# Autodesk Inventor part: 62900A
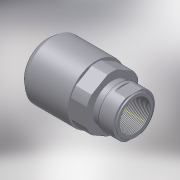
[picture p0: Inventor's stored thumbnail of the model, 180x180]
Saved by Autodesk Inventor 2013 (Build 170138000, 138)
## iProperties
Shininess: 25.0
Length Units: 11269
Angle Units: 11279
Time Units: 11290
Mass Units: 11283
Length Display Precision: 3
Angle Display Precision: 2
Created: 2002-07
Part Number: 62900A
Description: Дроссель с обратным клапаном 62900А ТУ22-5817-84
Document SubType Name: Modeling
Designer: SaAlex
Material: Steel, Mild
Density: 7.86 g/cm^3
Density: 0.0
Volumn: 0.0
Area: 0.0
PropertySet Name: Model Information
Control State: 0
Master: False
Checked Out: False
Checked Out Date: 2008-10-15
Last Check In Date: 2008-10-15
Author: SaAlex
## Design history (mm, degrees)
sketch "Sketch1"
  geometry: L1 (-67, 45)-(0, 45); L2 (-77, 36.5)-(-67, 45); L3 (-77, 36.5)-(-77, 32.5); L4 (-79, 32.5)-(-77, 32.5); L5 (-79, 30)-(-79, 32.5); L6 (-81, 30)-(-79, 30); L7 (-81, 0)-(-81, 30); L8 (-81, 0)-(0, 0); L9 (0, 45)-(0, 0); L10 (-81, 0)-(0, 0)
  constraints: 20 end point, 4 horizontal, 3 vertical, 1 other
  dimensions: "d67" = 81 distance between parallel lines of L9 L7; "d68" = 2 distance between parallel lines of L5 L7; "d69" = 2 distance between parallel lines of L3 L5; "d70" = 14 distance from line of L1.start L7; "d71" = 30 distance between parallel lines of L8 L6; "d72" = 32.5 distance between parallel lines of L8 L4; "d73" = 36.5 distance from line of L8 L2.start; "d75" = 45 distance from line of L8 L1.start
revolve "RevolutionFull1" sketch "Sketch1" stored, may be unused: angle "d0" = 360 deg
sketch "Sketch2"
  geometry: L1 (41.822, 7.563)-(27.46, 32.437); L2 (27.46, -32.437)-(41.822, -7.563); L3 (-14.361, -40)-(14.361, -40); L4 (-41.822, -7.563)-(-27.46, -32.437); L5 (-27.46, 32.437)-(-41.822, 7.563); L6 (14.361, 40)-(-14.361, 40); C1 r 40 at (0, 0); C2 r 45 at (0, 0) reference; A1 r 42.5 centre (0, 0) between (41.822, -7.563) and (41.822, 7.563); A2 r 42.5 centre (0, 0) between (14.361, -40) and (27.46, -32.437); A3 r 42.5 centre (0, 0) between (-27.46, -32.437) and (-14.361, -40); A4 r 42.5 centre (0, 0) between (-41.822, 7.563) and (-41.822, -7.563); A5 r 42.5 centre (0, 0) between (-14.361, 40) and (-27.46, 32.437); A6 r 42.5 centre (0, 0) between (27.46, 32.437) and (14.361, 40)
  constraints: 12 end point, 12 point on circle, 8 concentric, 7 centre point, 6 tangent, 2 horizontal, 1 coincident, 1 parallel
  dimensions: "d4" = 80 diameter of C1; "d6" = 42.5 radius of A5
extrude "ExtrusionBlind1" join sketch "Sketch2" distance "d7" = 25; taper "d8" = 0 deg
sketch "Sketch3"
  geometry: L1 (-29, 0)-(21, 0)
  constraints: 2 end point
node "WorkAxis1"
sketch "Sketch4"
  geometry: L1 (-25, 0)-(-36, 0); L2 (-25, 30)-(-25, 0); L3 (-36, 30)-(-25, 30); L4 (-36, 0)-(-36, 30); L5 (-25, -42.5)-(-25, -41.822) reference; L6 (-25, 0)-(-36, 0); L7 (104.4, 0)-(-59.4, 0) reference
  constraints: 10 end point, 2 collinear, 2 horizontal, 2 vertical
  dimensions: "d12" = 11 distance of L3.start L2.start; "d14" = 60 diameter of L3.start L1
revolve "RevolutionFull2" sketch "Sketch4" stored, may be unused: angle "d15" = 360 deg
sketch "Sketch5"
  geometry: L1 (-36, 0)-(-41, 0); L2 (-36, 32.5)-(-36, 0); L3 (-41, 32.5)-(-36, 32.5); L4 (-41, 0)-(-41, 32.5); L5 (-36, -30)-(-36, 30) reference; L6 (-36, 0)-(-41, 0)
  constraints: 10 end point, 2 horizontal, 2 vertical, 1 collinear
  dimensions: "d17" = 5 distance of L3.start L2.start; "d19" = 65 diameter of L3.start L1
revolve "RevolutionFull3" sketch "Sketch5" stored, may be unused: angle "d20" = 360 deg
sketch "Sketch6"
  geometry: L1 (41, 32.5)-(41, 0); L2 (59, 32.5)-(41, 32.5); L3 (59, 0)-(59, 32.5); L4 (41, 0)-(59, 0); L5 (41, 32.5)-(41, -32.5) reference; L6 (-92.53, 0)-(84.53, 0); L7 (41, 0)-(59, 0)
  constraints: 12 end point, 2 collinear, 2 horizontal, 2 vertical
  dimensions: "d23" = 32.5 distance of L3.start L2.start; "d25" = 18 distance of L2.start L5.start
revolve "RevolutionFull4" sketch "Sketch6" stored, may be unused: angle "d26" = 360 deg
sketch "Sketch7"
  geometry: L1 (-30, -37.13)-(-40, -37.13); L2 (-30, 22.87)-(-30, -37.13); L3 (-40, 22.87)-(-30, 22.87); L4 (-40, -37.13)-(-40, 22.87); C1 r 30 at (0, 0) reference
  constraints: 8 end point, 2 horizontal, 2 vertical
  dimensions: "d31" = 30 horizontal distance of L2.start C1.centre; "d33" = 60 distance of L1.end L3.start; "d35" = 10 distance of L1.start L1.end
extrude "ExtrusionBlind2" cut sketch "Sketch7" distance "d36" = 18; taper "d37" = 0 deg
pattern_circular "PolarArray1" dims angle "d40" = 360 deg
sketch "Sketch9"
  geometry: L1 (59, 29)-(59, 0); L2 (61, 29)-(59, 29); L3 (61, 0)-(61, 29); L4 (59, 0)-(61, 0); L5 (59, 12.5)-(59, 32.5) reference; L6 (-92.53, 0)-(84.53, 0); L7 (59, 0)-(61, 0)
  constraints: 12 end point, 2 collinear, 2 horizontal, 2 vertical
  dimensions: "d45" = 2 distance of L1.end L3.start; "d47" = 29 distance of L3.start L2.start
revolve "RevolutionFull6" sketch "Sketch9" stored, may be unused: angle "d48" = 360 deg
sketch "Sketch10"
  geometry: C1 r 30 at (0, 0) reference
hole "Hole1" sketch "Sketch10" diameter "d49" = 48; stored, may be unused: countersink angle "d53" = 82 deg, drill point angle "d55" = 120 deg; dims "d50" = 35, "d51" = 4, "d52" = 2, "d54" = 40
sketch "Sketch11"
  geometry: C1 r 29 at (0, 0) reference; 1 further point
hole "Hole2" sketch "Sketch11" at (0, 0) diameter "d57" = 48; stored, may be unused: countersink angle "d61" = 82 deg, drill point angle "d63" = 120 deg; dims "d58" = 35, "d59" = 4, "d60" = 2, "d62" = 40
feature "Резьба1" dims "d76" = 10, "d77" = 0
feature "Резьба2" dims "d78" = 10, "d79" = 0
sketch "Sketch12"
  geometry: L1 (0, 28.723)-(0, 0) reference; L2 (25, 28.723)-(0, 28.723) reference; L3 (5, 15.723)-(20, 15.723); L4 (20, 15.723)-(20, 17.223); L5 (20, 17.223)-(24.289, 15.223); L6 (24.289, 15.223)-(20, 13.223); L7 (20, 13.223)-(20, 14.723); L8 (20, 14.723)-(5, 14.723); L9 (5, 14.723)-(5, 15.723); L10 (8, 17.723)-(8.325, 18.103); L11 (14.325, 18.103)-(14.713, 17.772); L12 (5, 15.223)-(24.289, 15.223); L13 (14.325, 12.343)-(14.713, 12.674); L14 (8, 12.723)-(8.325, 12.343); A1 r 5.499 centre (11.325, 22.103) between (8, 17.723) and (14.713, 17.772); A2 r 5 centre (11.325, 22.103) between (8.325, 18.103) and (14.325, 18.103); A3 r 5 centre (11.325, 8.343) between (14.325, 12.343) and (8.325, 12.343); A4 r 5.499 centre (11.325, 8.343) between (14.713, 12.674) and (8, 12.723)
  constraints: 24 end point, 8 point on circle, 5 symmetric about line, 4 centre point, 3 parallel, 2 perpendicular, 1 collinear, 1 midpoint, 2 other
  dimensions: "d80" = 1 distance between parallel lines of L3 L8; "d81" = 13 distance between parallel lines of L2 L3; "d82" = 5 distance between parallel lines of L1 L9; "d83" = 15 distance between parallel lines of L7 L9; "d84" = 4 distance of L4.end L6.end; "d85" = 1.5 distance from line of L8 L6.end; "d86" = 2 vertical distance of L6.end L5.end; "d87" = 50 deg angle of L5 L6; "d88" = 0 distance between parallel lines of L4 L7; "d89" = 0.5 distance of L10.start L10.end; "d90" = 5 radius of A2; "d91" = 0 vertical distance of L10.end L11.start; "d92" = 2 distance from line of L10.start L3; "d93" = 3 horizontal distance of L10.start L3.start; "d94" = 6 distance of L11.start L10.end
extrude "Extrusion3" cut sketch "Sketch12" distance "d95" = 0.5; taper "d96" = 0 deg
body "Solid1"
other parameters: "d1" = 0, "d2" = 0, "d5" = 42.5 (derived), "d9" = 0, "d10" = 0, "d11" = 11 (derived), "d16" = 5 (derived), "d18" = 65 (derived), "d21" = 0, "d22" = 32.5 (derived), "d24" = 18 (derived), "d27" = 0, "d28" = 0, "d29" = 0, "d41" = 2 (derived), "d44" = 2 (derived), "d46" = 29 (derived), "d56" = 0
